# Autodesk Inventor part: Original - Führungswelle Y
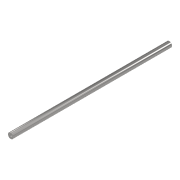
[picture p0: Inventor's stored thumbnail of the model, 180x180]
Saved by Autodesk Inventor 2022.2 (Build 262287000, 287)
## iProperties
Created: 2024-09
Part Number: Original - Führungswelle Y
Material: Acciaio inossidabile
Document SubType Name: Modeling
Designer: 18907419
Density: 8 g/cm^3
Appearance: Semilucidato
Author: 18907419
Revision Number: ANY
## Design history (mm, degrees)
feature "Fase1"
node "Solido1"
